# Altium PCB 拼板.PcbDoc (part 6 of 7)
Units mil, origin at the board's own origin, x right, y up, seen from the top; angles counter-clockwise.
Board outline 3630.03 x 5330.03 mil, 2 copper layers (Top Layer, Bottom Layer); 416 components, 35 nets, 1936 pads, 800 vias.
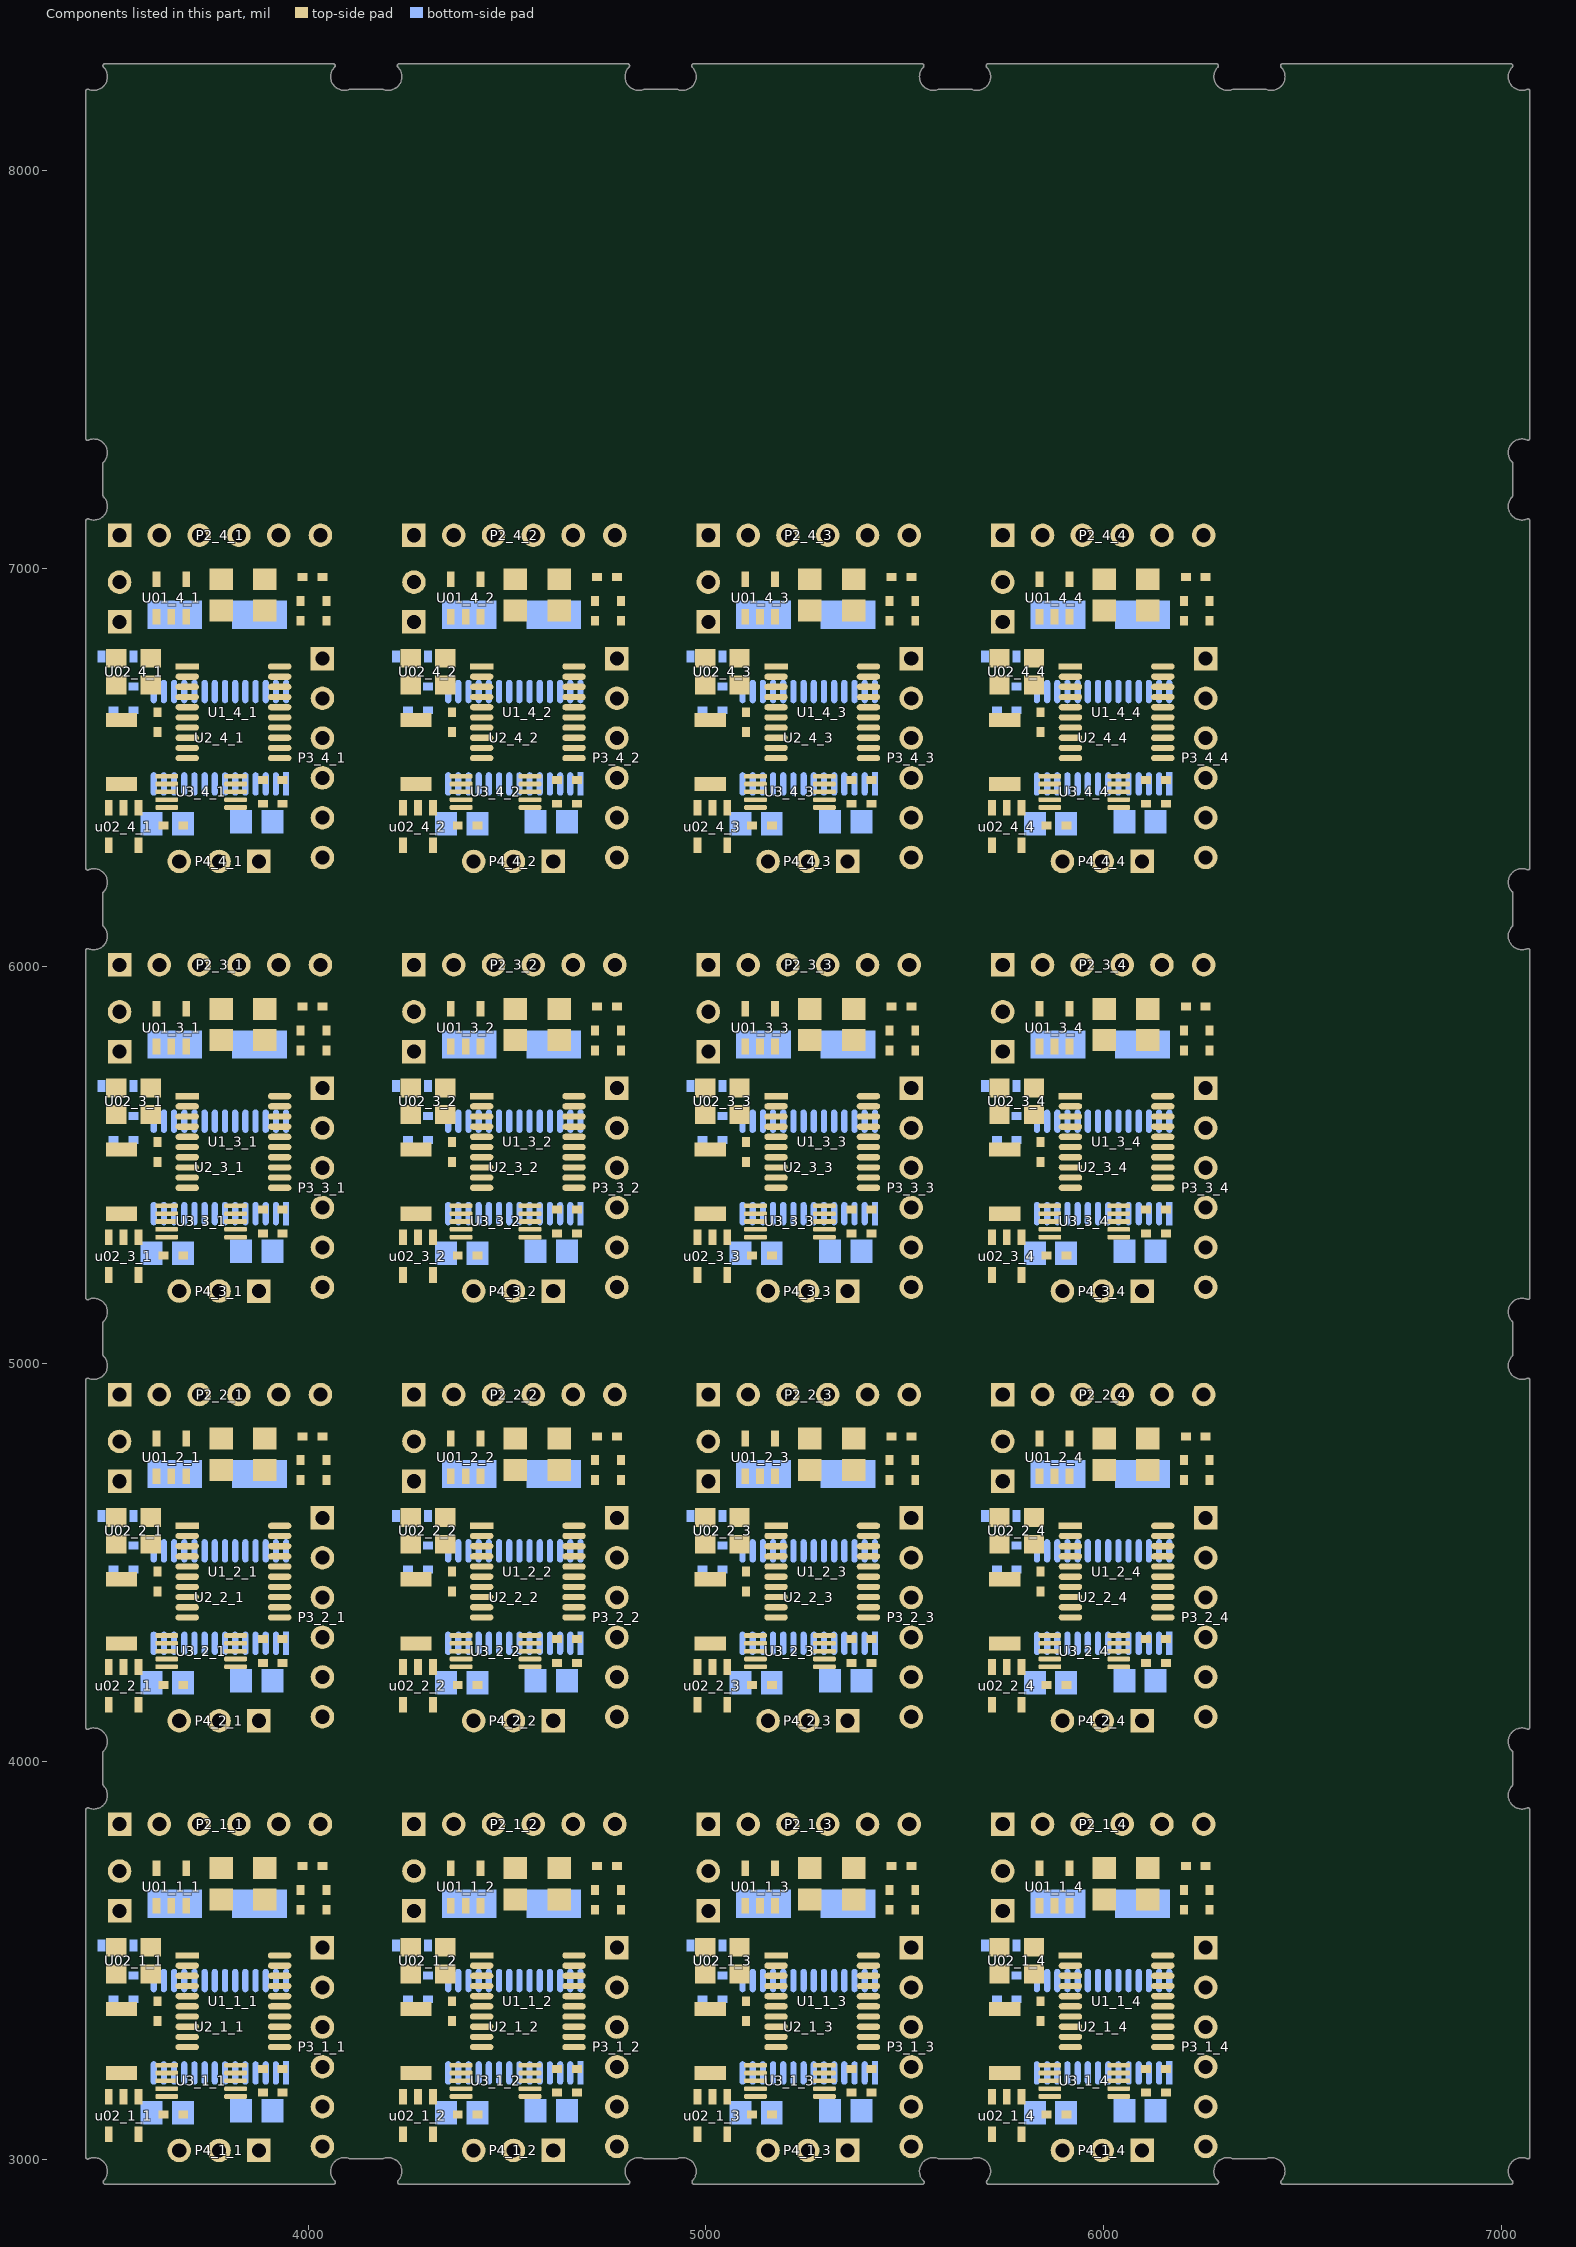
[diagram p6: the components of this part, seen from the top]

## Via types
v1: diameter 24, hole 24, Top Layer to Bottom Layer, 480 vias
v2: diameter 20, hole 10, Top Layer to Bottom Layer, 240 vias
v3: diameter 36, hole 20, Top Layer to Bottom Layer, 48 vias
v4: diameter 32, hole 16, Top Layer to Bottom Layer, 32 vias

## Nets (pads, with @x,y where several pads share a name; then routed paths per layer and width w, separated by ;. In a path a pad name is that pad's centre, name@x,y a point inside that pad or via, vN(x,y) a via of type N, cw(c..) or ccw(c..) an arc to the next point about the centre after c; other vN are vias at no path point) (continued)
copper on no net: (continued)
  Bottom Layer w20: 3506.07,3463.02 3517.35,3463.02 3542.35,3488.02 3557.28,3488.02 3592.28,3523.02 3936.07,3523.02 ; 3506.07,4543.02 3517.35,4543.02 3542.35,4568.02 3557.28,4568.02 3592.28,4603.02 3936.07,4603.02 ; 3506.07,5623.02 3517.35,5623.02 3542.35,5648.02 3557.28,5648.02 3592.28,5683.02 3936.07,5683.02 ; 3506.07,6703.02 3517.35,6703.02 3542.35,6728.02 3557.28,6728.02 3592.28,6763.02 3936.07,6763.02 ; v3(3537.32,3264.27) 3582.8,3264.27 3611.93,3235.14 3611.93,3217.74 3611.93,3123.26 3606.7,3118.02 3606.7,3029.42 3657.62,2978.49 3814.35,2978.49 ; v3(3537.32,4344.27) 3582.8,4344.27 3611.93,4315.14 3611.93,4297.74 3611.93,4203.26 3606.7,4198.02 3606.7,4109.42 3657.62,4058.49 3814.35,4058.49 ; v3(3537.32,5424.27) 3582.8,5424.27 3611.93,5395.14 3611.93,5377.74 3611.93,5283.26 3606.7,5278.02 3606.7,5189.42 3657.62,5138.49 3814.35,5138.49 ; v3(3537.32,6504.27) 3582.8,6504.27 3611.93,6475.14 3611.93,6457.74 3611.93,6363.26 3606.7,6358.02 3606.7,6269.42 3657.62,6218.49 3814.35,6218.49 ; 3664.77,3643.02 3631.3,3643.02 3605.87,3617.59 3605.87,3587.83 3561.07,3543.02 3561.07,3538.02 3556.07,3533.02 3551.07,3533.02 3522.78,3504.74 3502.78,3504.74 3466.07,3468.02 3466.07,3378.02 3491.07,3353.02 3601.07,3353.02 3693.11,3260.98 ; 3664.77,4723.02 3631.3,4723.02 3605.87,4697.59 3605.87,4667.83 3561.07,4623.02 3561.07,4618.02 3556.07,4613.02 3551.07,4613.02 3522.78,4584.74 3502.78,4584.74 3466.07,4548.02 3466.07,4458.02 3491.07,4433.02 3601.07,4433.02 3693.11,4340.98 ; 3664.77,5803.02 3631.3,5803.02 3605.87,5777.59 3605.87,5747.83 3561.07,5703.02 3561.07,5698.02 3556.07,5693.02 3551.07,5693.02 3522.78,5664.74 3502.78,5664.74 3466.07,5628.02 3466.07,5538.02 3491.07,5513.02 3601.07,5513.02 3693.11,5420.98 ; 3664.77,6883.02 3631.3,6883.02 3605.87,6857.59 3605.87,6827.83 3561.07,6783.02 3561.07,6778.02 3556.07,6773.02 3551.07,6773.02 3522.78,6744.74 3502.78,6744.74 3466.07,6708.02 3466.07,6618.02 3491.07,6593.02 3601.07,6593.02 3693.11,6500.98 ; 3688.7,3217.74 3688.7,3245.38 3688.7,3256.58 3694.39,3262.27 3772.09,3262.27 3772.84,3263.02 3854.87,3263.02 v3(3857.87,3266.02) ; 3688.7,4297.74 3688.7,4325.38 3688.7,4336.58 3694.39,4342.27 3772.09,4342.27 3772.84,4343.02 3854.87,4343.02 v3(3857.87,4346.02) ; 3688.7,5377.74 3688.7,5405.38 3688.7,5416.58 3694.39,5422.27 3772.09,5422.27 3772.84,5423.02 3854.87,5423.02 v3(3857.87,5426.02) ; 3688.7,6457.74 3688.7,6485.38 3688.7,6496.58 3694.39,6502.27 3772.09,6502.27 3772.84,6503.02 3854.87,6503.02 v3(3857.87,6506.02) ; 3739.89,3450.02 3739.89,3409.2 3801.07,3348.02 3897.28,3348.02 3944.61,3395.35 3944.61,3467.43 3972.49,3467.43 4016.54,3511.47 4016.54,3513.49 4021.07,3518.02 ; 3739.89,4530.02 3739.89,4489.2 3801.07,4428.02 3897.28,4428.02 3944.61,4475.35 3944.61,4547.43 3972.49,4547.43 4016.54,4591.47 4016.54,4593.49 4021.07,4598.02 ; 3739.89,5610.02 3739.89,5569.2 3801.07,5508.02 3897.28,5508.02 3944.61,5555.35 3944.61,5627.43 3972.49,5627.43 4016.54,5671.47 4016.54,5673.49 4021.07,5678.02 ; 3739.89,6690.02 3739.89,6649.2 3801.07,6588.02 3897.28,6588.02 3944.61,6635.35 3944.61,6707.43 3972.49,6707.43 4016.54,6751.47 4016.54,6753.49 4021.07,6758.02 ; 3791.07,3217.74 3791.07,3160.69 3789.14,3158.76 3789.14,3087.28 3797.92,3078.49 3821.07,3078.49 ; 3791.07,4297.74 3791.07,4240.69 3789.14,4238.76 3789.14,4167.28 3797.92,4158.49 3821.07,4158.49 ; 3791.07,5377.74 3791.07,5320.69 3789.14,5318.76 3789.14,5247.28 3797.92,5238.49 3821.07,5238.49 ; 3791.07,6457.74 3791.07,6400.69 3789.14,6398.76 3789.14,6327.28 3797.92,6318.49 3821.07,6318.49 ; v3@3866.88,3262.27 3867.84,3261.31 3867.84,3217.74 ; v3@3866.88,4342.27 3867.84,4341.31 3867.84,4297.74 ; v3@3866.88,5422.27 3867.84,5421.31 3867.84,5377.74 ; v3@3866.88,6502.27 3867.84,6501.31 3867.84,6457.74 ; 3877.37,3643.02 3877.37,3581.72 3936.07,3523.02 ; 3877.37,4723.02 3877.37,4661.72 3936.07,4603.02 ; 3877.37,5803.02 3877.37,5741.72 3936.07,5683.02 ; 3877.37,6883.02 3877.37,6821.72 3936.07,6763.02 ; 3910.44,3123.02 3910.44,3121.05 3867.88,3078.49 3821.07,3078.49 ; 3910.44,4203.02 3910.44,4201.05 3867.88,4158.49 3821.07,4158.49 ; 3910.44,5283.02 3910.44,5281.05 3867.88,5238.49 3821.07,5238.49 ; 3910.44,6363.02 3910.44,6361.05 3867.88,6318.49 3821.07,6318.49 ; v3(4036.07,3713.02) 4036.07,3533.02 ; v3(4036.07,4793.02) 4036.07,4613.02 ; v3(4036.07,5873.02) 4036.07,5693.02 ; v3(4036.07,6953.02) 4036.07,6773.02 ; 4246.07,3463.02 4257.35,3463.02 4282.35,3488.02 4297.28,3488.02 4332.28,3523.02 4676.07,3523.02 ; 4246.07,4543.02 4257.35,4543.02 4282.35,4568.02 4297.28,4568.02 4332.28,4603.02 4676.07,4603.02 ; 4246.07,5623.02 4257.35,5623.02 4282.35,5648.02 4297.28,5648.02 4332.28,5683.02 4676.07,5683.02 ; 4246.07,6703.02 4257.35,6703.02 4282.35,6728.02 4297.28,6728.02 4332.28,6763.02 4676.07,6763.02 ; v3(4277.32,3264.27) 4322.8,3264.27 4351.93,3235.14 4351.93,3217.74 4351.93,3123.26 4346.7,3118.02 4346.7,3029.42 4397.62,2978.49 4554.35,2978.49 ; v3(4277.32,4344.27) 4322.8,4344.27 4351.93,4315.14 4351.93,4297.74 4351.93,4203.26 4346.7,4198.02 4346.7,4109.42 4397.62,4058.49 4554.35,4058.49 ; v3(4277.32,5424.27) 4322.8,5424.27 4351.93,5395.14 4351.93,5377.74 4351.93,5283.26 4346.7,5278.02 4346.7,5189.42 4397.62,5138.49 4554.35,5138.49 ; v3(4277.32,6504.27) 4322.8,6504.27 4351.93,6475.14 4351.93,6457.74 4351.93,6363.26 4346.7,6358.02 4346.7,6269.42 4397.62,6218.49 4554.35,6218.49 ; 4404.77,3643.02 4371.3,3643.02 4345.87,3617.59 4345.87,3587.83 4301.07,3543.02 4301.07,3538.02 4296.07,3533.02 4291.07,3533.02 4262.78,3504.74 4242.78,3504.74 4206.07,3468.02 4206.07,3378.02 4231.07,3353.02 4341.07,3353.02 4433.11,3260.98 ; 4404.77,4723.02 4371.3,4723.02 4345.87,4697.59 4345.87,4667.83 4301.07,4623.02 4301.07,4618.02 4296.07,4613.02 4291.07,4613.02 4262.78,4584.74 4242.78,4584.74 4206.07,4548.02 4206.07,4458.02 4231.07,4433.02 4341.07,4433.02 4433.11,4340.98 ; 4404.77,5803.02 4371.3,5803.02 4345.87,5777.59 4345.87,5747.83 4301.07,5703.02 4301.07,5698.02 4296.07,5693.02 4291.07,5693.02 4262.78,5664.74 4242.78,5664.74 4206.07,5628.02 4206.07,5538.02 4231.07,5513.02 4341.07,5513.02 4433.11,5420.98 ; 4404.77,6883.02 4371.3,6883.02 4345.87,6857.59 4345.87,6827.83 4301.07,6783.02 4301.07,6778.02 4296.07,6773.02 4291.07,6773.02 4262.78,6744.74 4242.78,6744.74 4206.07,6708.02 4206.07,6618.02 4231.07,6593.02 4341.07,6593.02 4433.11,6500.98 ; 4428.7,3217.74 4428.7,3245.38 4428.7,3256.58 4434.39,3262.27 4512.09,3262.27 4512.84,3263.02 4594.87,3263.02 v3(4597.87,3266.02) ; 4428.7,4297.74 4428.7,4325.38 4428.7,4336.58 4434.39,4342.27 4512.09,4342.27 4512.84,4343.02 4594.87,4343.02 v3(4597.87,4346.02) ; 4428.7,5377.74 4428.7,5405.38 4428.7,5416.58 4434.39,5422.27 4512.09,5422.27 4512.84,5423.02 4594.87,5423.02 v3(4597.87,5426.02) ; 4428.7,6457.74 4428.7,6485.38 4428.7,6496.58 4434.39,6502.27 4512.09,6502.27 4512.84,6503.02 4594.87,6503.02 v3(4597.87,6506.02) ; 4479.89,3450.02 4479.89,3409.2 4541.07,3348.02 4637.28,3348.02 4684.61,3395.35 4684.61,3467.43 4712.49,3467.43 4756.54,3511.47 4756.54,3513.49 4761.07,3518.02 ; 4479.89,4530.02 4479.89,4489.2 4541.07,4428.02 4637.28,4428.02 4684.61,4475.35 4684.61,4547.43 4712.49,4547.43 4756.54,4591.47 4756.54,4593.49 4761.07,4598.02 ; 4479.89,5610.02 4479.89,5569.2 4541.07,5508.02 4637.28,5508.02 4684.61,5555.35 4684.61,5627.43 4712.49,5627.43 4756.54,5671.47 4756.54,5673.49 4761.07,5678.02 ; 4479.89,6690.02 4479.89,6649.2 4541.07,6588.02 4637.28,6588.02 4684.61,6635.35 4684.61,6707.43 4712.49,6707.43 4756.54,6751.47 4756.54,6753.49 4761.07,6758.02 ; 4531.07,3217.74 4531.07,3160.69 4529.14,3158.76 4529.14,3087.28 4537.92,3078.49 4561.07,3078.49 ; 4531.07,4297.74 4531.07,4240.69 4529.14,4238.76 4529.14,4167.28 4537.92,4158.49 4561.07,4158.49 ; 4531.07,5377.74 4531.07,5320.69 4529.14,5318.76 4529.14,5247.28 4537.92,5238.49 4561.07,5238.49 ; 4531.07,6457.74 4531.07,6400.69 4529.14,6398.76 4529.14,6327.28 4537.92,6318.49 4561.07,6318.49 ; v3@4606.88,3262.27 4607.84,3261.31 4607.84,3217.74 ; v3@4606.88,4342.27 4607.84,4341.31 4607.84,4297.74 ; v3@4606.88,5422.27 4607.84,5421.31 4607.84,5377.74 ; v3@4606.88,6502.27 4607.84,6501.31 4607.84,6457.74 ; 4617.37,3643.02 4617.37,3581.72 4676.07,3523.02 ; 4617.37,4723.02 4617.37,4661.72 4676.07,4603.02 ; 4617.37,5803.02 4617.37,5741.72 4676.07,5683.02 ; 4617.37,6883.02 4617.37,6821.72 4676.07,6763.02 ; 4650.44,3123.02 4650.44,3121.05 4607.88,3078.49 4561.07,3078.49 ; 4650.44,4203.02 4650.44,4201.05 4607.88,4158.49 4561.07,4158.49 ; 4650.44,5283.02 4650.44,5281.05 4607.88,5238.49 4561.07,5238.49 ; 4650.44,6363.02 4650.44,6361.05 4607.88,6318.49 4561.07,6318.49 ; v3(4776.07,3713.02) 4776.07,3533.02 ; v3(4776.07,4793.02) 4776.07,4613.02 ; v3(4776.07,5873.02) 4776.07,5693.02 ; v3(4776.07,6953.02) 4776.07,6773.02 ; 4986.07,3463.02 4997.35,3463.02 5022.35,3488.02 5037.28,3488.02 5072.28,3523.02 5416.07,3523.02 ; 4986.07,4543.02 4997.35,4543.02 5022.35,4568.02 5037.28,4568.02 5072.28,4603.02 5416.07,4603.02 ; 4986.07,5623.02 4997.35,5623.02 5022.35,5648.02 5037.28,5648.02 5072.28,5683.02 5416.07,5683.02 ; 4986.07,6703.02 4997.35,6703.02 5022.35,6728.02 5037.28,6728.02 5072.28,6763.02 5416.07,6763.02 ; v3(5017.32,3264.27) 5062.8,3264.27 5091.93,3235.14 5091.93,3217.74 5091.93,3123.26 5086.7,3118.02 5086.7,3029.42 5137.62,2978.49 5294.35,2978.49 ; v3(5017.32,4344.27) 5062.8,4344.27 5091.93,4315.14 5091.93,4297.74 5091.93,4203.26 5086.7,4198.02 5086.7,4109.42 5137.62,4058.49 5294.35,4058.49 ; v3(5017.32,5424.27) 5062.8,5424.27 5091.93,5395.14 5091.93,5377.74 5091.93,5283.26 5086.7,5278.02 5086.7,5189.42 5137.62,5138.49 5294.35,5138.49 ; v3(5017.32,6504.27) 5062.8,6504.27 5091.93,6475.14 5091.93,6457.74 5091.93,6363.26 5086.7,6358.02 5086.7,6269.42 5137.62,6218.49 5294.35,6218.49 ; 5144.77,3643.02 5111.3,3643.02 5085.87,3617.59 5085.87,3587.83 5041.07,3543.02 5041.07,3538.02 5036.07,3533.02 5031.07,3533.02 5002.78,3504.74 4982.78,3504.74 4946.07,3468.02 4946.07,3378.02 4971.07,3353.02 5081.07,3353.02 5173.11,3260.98 ; 5144.77,4723.02 5111.3,4723.02 5085.87,4697.59 5085.87,4667.83 5041.07,4623.02 5041.07,4618.02 5036.07,4613.02 5031.07,4613.02 5002.78,4584.74 4982.78,4584.74 4946.07,4548.02 4946.07,4458.02 4971.07,4433.02 5081.07,4433.02 5173.11,4340.98 ; 5144.77,5803.02 5111.3,5803.02 5085.87,5777.59 5085.87,5747.83 5041.07,5703.02 5041.07,5698.02 5036.07,5693.02 5031.07,5693.02 5002.78,5664.74 4982.78,5664.74 4946.07,5628.02 4946.07,5538.02 4971.07,5513.02 5081.07,5513.02 5173.11,5420.98 ; 5144.77,6883.02 5111.3,6883.02 5085.87,6857.59 5085.87,6827.83 5041.07,6783.02 5041.07,6778.02 5036.07,6773.02 5031.07,6773.02 5002.78,6744.74 4982.78,6744.74 4946.07,6708.02 4946.07,6618.02 4971.07,6593.02 5081.07,6593.02 5173.11,6500.98 ; 5168.7,3217.74 5168.7,3245.38 5168.7,3256.58 5174.39,3262.27 5252.09,3262.27 5252.84,3263.02 5334.87,3263.02 v3(5337.87,3266.02) ; 5168.7,4297.74 5168.7,4325.38 5168.7,4336.58 5174.39,4342.27 5252.09,4342.27 5252.84,4343.02 5334.87,4343.02 v3(5337.87,4346.02) ; 5168.7,5377.74 5168.7,5405.38 5168.7,5416.58 5174.39,5422.27 5252.09,5422.27 5252.84,5423.02 5334.87,5423.02 v3(5337.87,5426.02) ; 5168.7,6457.74 5168.7,6485.38 5168.7,6496.58 5174.39,6502.27 5252.09,6502.27 5252.84,6503.02 5334.87,6503.02 v3(5337.87,6506.02) ; 5219.89,3450.02 5219.89,3409.2 5281.07,3348.02 5377.28,3348.02 5424.61,3395.35 5424.61,3467.43 5452.49,3467.43 5496.54,3511.47 5496.54,3513.49 5501.07,3518.02 ; 5219.89,4530.02 5219.89,4489.2 5281.07,4428.02 5377.28,4428.02 5424.61,4475.35 5424.61,4547.43 5452.49,4547.43 5496.54,4591.47 5496.54,4593.49 5501.07,4598.02 ; 5219.89,5610.02 5219.89,5569.2 5281.07,5508.02 5377.28,5508.02 5424.61,5555.35 5424.61,5627.43 5452.49,5627.43 5496.54,5671.47 5496.54,5673.49 5501.07,5678.02 ; 5219.89,6690.02 5219.89,6649.2 5281.07,6588.02 5377.28,6588.02 5424.61,6635.35 5424.61,6707.43 5452.49,6707.43 5496.54,6751.47 5496.54,6753.49 5501.07,6758.02 ; 5271.07,3217.74 5271.07,3160.69 5269.14,3158.76 5269.14,3087.28 5277.92,3078.49 5301.07,3078.49 ; 5271.07,4297.74 5271.07,4240.69 5269.14,4238.76 5269.14,4167.28 5277.92,4158.49 5301.07,4158.49 ; 5271.07,5377.74 5271.07,5320.69 5269.14,5318.76 5269.14,5247.28 5277.92,5238.49 5301.07,5238.49 ; 5271.07,6457.74 5271.07,6400.69 5269.14,6398.76 5269.14,6327.28 5277.92,6318.49 5301.07,6318.49 ; v3@5346.88,3262.27 5347.84,3261.31 5347.84,3217.74 ; v3@5346.88,4342.27 5347.84,4341.31 5347.84,4297.74 ; v3@5346.88,5422.27 5347.84,5421.31 5347.84,5377.74 ; v3@5346.88,6502.27 5347.84,6501.31 5347.84,6457.74 ; 5357.37,3643.02 5357.37,3581.72 5416.07,3523.02 ; 5357.37,4723.02 5357.37,4661.72 5416.07,4603.02 ; 5357.37,5803.02 5357.37,5741.72 5416.07,5683.02 ; 5357.37,6883.02 5357.37,6821.72 5416.07,6763.02 ; 5390.44,3123.02 5390.44,3121.05 5347.88,3078.49 5301.07,3078.49 ; 5390.44,4203.02 5390.44,4201.05 5347.88,4158.49 5301.07,4158.49 ; 5390.44,5283.02 5390.44,5281.05 5347.88,5238.49 5301.07,5238.49 ; 5390.44,6363.02 5390.44,6361.05 5347.88,6318.49 5301.07,6318.49 ; v3(5516.07,3713.02) 5516.07,3533.02 ; v3(5516.07,4793.02) 5516.07,4613.02 ; v3(5516.07,5873.02) 5516.07,5693.02 ; v3(5516.07,6953.02) 5516.07,6773.02 ; 5726.07,3463.02 5737.35,3463.02 5762.35,3488.02 5777.28,3488.02 5812.28,3523.02 6156.07,3523.02 ; 5726.07,4543.02 5737.35,4543.02 5762.35,4568.02 5777.28,4568.02 5812.28,4603.02 6156.07,4603.02 ; 5726.07,5623.02 5737.35,5623.02 5762.35,5648.02 5777.28,5648.02 5812.28,5683.02 6156.07,5683.02 ; 5726.07,6703.02 5737.35,6703.02 5762.35,6728.02 5777.28,6728.02 5812.28,6763.02 6156.07,6763.02 ; v3(5757.32,3264.27) 5802.8,3264.27 5831.93,3235.14 5831.93,3217.74 5831.93,3123.26 5826.7,3118.02 5826.7,3029.42 5877.62,2978.49 6034.35,2978.49 ; v3(5757.32,4344.27) 5802.8,4344.27 5831.93,4315.14 5831.93,4297.74 5831.93,4203.26 5826.7,4198.02 5826.7,4109.42 5877.62,4058.49 6034.35,4058.49 ; v3(5757.32,5424.27) 5802.8,5424.27 5831.93,5395.14 5831.93,5377.74 5831.93,5283.26 5826.7,5278.02 5826.7,5189.42 5877.62,5138.49 6034.35,5138.49 ; v3(5757.32,6504.27) 5802.8,6504.27 5831.93,6475.14 5831.93,6457.74 5831.93,6363.26 5826.7,6358.02 5826.7,6269.42 5877.62,6218.49 6034.35,6218.49 ; 5884.77,3643.02 5851.3,3643.02 5825.87,3617.59 5825.87,3587.83 5781.07,3543.02 5781.07,3538.02 5776.07,3533.02 5771.07,3533.02 5742.78,3504.74 5722.78,3504.74 5686.07,3468.02 5686.07,3378.02 5711.07,3353.02 5821.07,3353.02 5913.11,3260.98 ; 5884.77,4723.02 5851.3,4723.02 5825.87,4697.59 5825.87,4667.83 5781.07,4623.02 5781.07,4618.02 5776.07,4613.02 5771.07,4613.02 5742.78,4584.74 5722.78,4584.74 5686.07,4548.02 5686.07,4458.02 5711.07,4433.02 5821.07,4433.02 5913.11,4340.98 ; 5884.77,5803.02 5851.3,5803.02 5825.87,5777.59 5825.87,5747.83 5781.07,5703.02 5781.07,5698.02 5776.07,5693.02 5771.07,5693.02 5742.78,5664.74 5722.78,5664.74 5686.07,5628.02 5686.07,5538.02 5711.07,5513.02 5821.07,5513.02 5913.11,5420.98 ; 5884.77,6883.02 5851.3,6883.02 5825.87,6857.59 5825.87,6827.83 5781.07,6783.02 5781.07,6778.02 5776.07,6773.02 5771.07,6773.02 5742.78,6744.74 5722.78,6744.74 5686.07,6708.02 5686.07,6618.02 5711.07,6593.02 5821.07,6593.02 5913.11,6500.98 ; 5908.7,3217.74 5908.7,3245.38 5908.7,3256.58 5914.39,3262.27 5992.09,3262.27 5992.84,3263.02 6074.87,3263.02 v3(6077.87,3266.02) ; 5908.7,4297.74 5908.7,4325.38 5908.7,4336.58 5914.39,4342.27 5992.09,4342.27 5992.84,4343.02 6074.87,4343.02 v3(6077.87,4346.02) ; 5908.7,5377.74 5908.7,5405.38 5908.7,5416.58 5914.39,5422.27 5992.09,5422.27 5992.84,5423.02 6074.87,5423.02 v3(6077.87,5426.02) ; 5908.7,6457.74 5908.7,6485.38 5908.7,6496.58 5914.39,6502.27 5992.09,6502.27 5992.84,6503.02 6074.87,6503.02 v3(6077.87,6506.02) ; 5959.89,3450.02 5959.89,3409.2 6021.07,3348.02 6117.28,3348.02 6164.61,3395.35 6164.61,3467.43 6192.49,3467.43 6236.54,3511.47 6236.54,3513.49 6241.07,3518.02 ; 5959.89,4530.02 5959.89,4489.2 6021.07,4428.02 6117.28,4428.02 6164.61,4475.35 6164.61,4547.43 6192.49,4547.43 6236.54,4591.47 6236.54,4593.49 6241.07,4598.02 ; 5959.89,5610.02 5959.89,5569.2 6021.07,5508.02 6117.28,5508.02 6164.61,5555.35 6164.61,5627.43 6192.49,5627.43 6236.54,5671.47 6236.54,5673.49 6241.07,5678.02 ; 5959.89,6690.02 5959.89,6649.2 6021.07,6588.02 6117.28,6588.02 6164.61,6635.35 6164.61,6707.43 6192.49,6707.43 6236.54,6751.47 6236.54,6753.49 6241.07,6758.02 ; 6011.07,3217.74 6011.07,3160.69 6009.14,3158.76 6009.14,3087.28 6017.92,3078.49 6041.07,3078.49 ; 6011.07,4297.74 6011.07,4240.69 6009.14,4238.76 6009.14,4167.28 6017.92,4158.49 6041.07,4158.49 ; 6011.07,5377.74 6011.07,5320.69 6009.14,5318.76 6009.14,5247.28 6017.92,5238.49 6041.07,5238.49 ; 6011.07,6457.74 6011.07,6400.69 6009.14,6398.76 6009.14,6327.28 6017.92,6318.49 6041.07,6318.49 ; v3@6086.88,3262.27 6087.84,3261.31 6087.84,3217.74 ; v3@6086.88,4342.27 6087.84,4341.31 6087.84,4297.74 ; v3@6086.88,5422.27 6087.84,5421.31 6087.84,5377.74 ; v3@6086.88,6502.27 6087.84,6501.31 6087.84,6457.74 ; 6097.37,3643.02 6097.37,3581.72 6156.07,3523.02 ; 6097.37,4723.02 6097.37,4661.72 6156.07,4603.02 ; 6097.37,5803.02 6097.37,5741.72 6156.07,5683.02 ; 6097.37,6883.02 6097.37,6821.72 6156.07,6763.02 ; 6130.44,3123.02 6130.44,3121.05 6087.88,3078.49 6041.07,3078.49 ; 6130.44,4203.02 6130.44,4201.05 6087.88,4158.49 6041.07,4158.49 ; 6130.44,5283.02 6130.44,5281.05 6087.88,5238.49 6041.07,5238.49 ; 6130.44,6363.02 6130.44,6361.05 6087.88,6318.49 6041.07,6318.49 ; v3(6256.07,3713.02) 6256.07,3533.02 ; v3(6256.07,4793.02) 6256.07,4613.02 ; v3(6256.07,5873.02) 6256.07,5693.02 ; v3(6256.07,6953.02) 6256.07,6773.02 ; 3814.35,2978.49 3821.07,2985.21 3821.07,3078.49 ; 3814.35,2978.49 3918.57,2978.49 4028.57,3088.49 4054.51,3088.49 4086.07,3120.05 4086.07,3483.02 4036.07,3533.02 ; 3814.35,4058.49 3821.07,4065.21 3821.07,4158.49 ; 3814.35,4058.49 3918.57,4058.49 4028.57,4168.49 4054.51,4168.49 4086.07,4200.05 4086.07,4563.02 4036.07,4613.02 ; 3814.35,5138.49 3821.07,5145.21 3821.07,5238.49 ; 3814.35,5138.49 3918.57,5138.49 4028.57,5248.49 4054.51,5248.49 4086.07,5280.05 4086.07,5643.02 4036.07,5693.02 ; 3814.35,6218.49 3821.07,6225.21 3821.07,6318.49 ; 3814.35,6218.49 3918.57,6218.49 4028.57,6328.49 4054.51,6328.49 4086.07,6360.05 4086.07,6723.02 4036.07,6773.02 ; 3936.07,3523.02 4016.54,3523.02 4021.07,3518.49 4021.07,3518.02 ; 3936.07,4603.02 4016.54,4603.02 4021.07,4598.49 4021.07,4598.02 ; 3936.07,5683.02 4016.54,5683.02 4021.07,5678.49 4021.07,5678.02 ; 3936.07,6763.02 4016.54,6763.02 4021.07,6758.49 4021.07,6758.02 ; 4021.07,3518.02 4036.07,3533.02 ; 4021.07,4598.02 4036.07,4613.02 ; 4021.07,5678.02 4036.07,5693.02 ; 4021.07,6758.02 4036.07,6773.02 ; 4554.35,2978.49 4561.07,2985.21 4561.07,3078.49 ; 4554.35,2978.49 4658.57,2978.49 4768.57,3088.49 4794.51,3088.49 4826.07,3120.05 4826.07,3483.02 4776.07,3533.02 ; 4554.35,4058.49 4561.07,4065.21 4561.07,4158.49 ; 4554.35,4058.49 4658.57,4058.49 4768.57,4168.49 4794.51,4168.49 4826.07,4200.05 4826.07,4563.02 4776.07,4613.02 ; 4554.35,5138.49 4561.07,5145.21 4561.07,5238.49 ; 4554.35,5138.49 4658.57,5138.49 4768.57,5248.49 4794.51,5248.49 4826.07,5280.05 4826.07,5643.02 4776.07,5693.02 ; 4554.35,6218.49 4561.07,6225.21 4561.07,6318.49 ; 4554.35,6218.49 4658.57,6218.49 4768.57,6328.49 4794.51,6328.49 4826.07,6360.05 4826.07,6723.02 4776.07,6773.02 ; 4676.07,3523.02 4756.54,3523.02 4761.07,3518.49 4761.07,3518.02 ; 4676.07,4603.02 4756.54,4603.02 4761.07,4598.49 4761.07,4598.02 ; 4676.07,5683.02 4756.54,5683.02 4761.07,5678.49 4761.07,5678.02 ; 4676.07,6763.02 4756.54,6763.02 4761.07,6758.49 4761.07,6758.02 ; 4761.07,3518.02 4776.07,3533.02 ; 4761.07,4598.02 4776.07,4613.02 ; 4761.07,5678.02 4776.07,5693.02 ; 4761.07,6758.02 4776.07,6773.02 ; 5294.35,2978.49 5301.07,2985.21 5301.07,3078.49 ; 5294.35,2978.49 5398.57,2978.49 5508.57,3088.49 5534.51,3088.49 5566.07,3120.05 5566.07,3483.02 5516.07,3533.02 ; 5294.35,4058.49 5301.07,4065.21 5301.07,4158.49 ; 5294.35,4058.49 5398.57,4058.49 5508.57,4168.49 5534.51,4168.49 5566.07,4200.05 5566.07,4563.02 5516.07,4613.02 ; 5294.35,5138.49 5301.07,5145.21 5301.07,5238.49 ; 5294.35,5138.49 5398.57,5138.49 5508.57,5248.49 5534.51,5248.49 5566.07,5280.05 5566.07,5643.02 5516.07,5693.02 ; 5294.35,6218.49 5301.07,6225.21 5301.07,6318.49 ; 5294.35,6218.49 5398.57,6218.49 5508.57,6328.49 5534.51,6328.49 5566.07,6360.05 5566.07,6723.02 5516.07,6773.02 ; 5416.07,3523.02 5496.54,3523.02 5501.07,3518.49 5501.07,3518.02 ; 5416.07,4603.02 5496.54,4603.02 5501.07,4598.49 5501.07,4598.02 ; 5416.07,5683.02 5496.54,5683.02 5501.07,5678.49 5501.07,5678.02 ; 5416.07,6763.02 5496.54,6763.02 5501.07,6758.49 5501.07,6758.02 ; 5501.07,3518.02 5516.07,3533.02 ; 5501.07,4598.02 5516.07,4613.02 ; 5501.07,5678.02 5516.07,5693.02 ; 5501.07,6758.02 5516.07,6773.02 ; 6034.35,2978.49 6041.07,2985.21 6041.07,3078.49 ; 6034.35,2978.49 6138.57,2978.49 6248.57,3088.49 6274.51,3088.49 6306.07,3120.05 6306.07,3483.02 6256.07,3533.02 ; 6034.35,4058.49 6041.07,4065.21 6041.07,4158.49 ; 6034.35,4058.49 6138.57,4058.49 6248.57,4168.49 6274.51,4168.49 6306.07,4200.05 6306.07,4563.02 6256.07,4613.02 ; 6034.35,5138.49 6041.07,5145.21 6041.07,5238.49 ; 6034.35,5138.49 6138.57,5138.49 6248.57,5248.49 6274.51,5248.49 6306.07,5280.05 6306.07,5643.02 6256.07,5693.02 ; 6034.35,6218.49 6041.07,6225.21 6041.07,6318.49 ; 6034.35,6218.49 6138.57,6218.49 6248.57,6328.49 6274.51,6328.49 6306.07,6360.05 6306.07,6723.02 6256.07,6773.02 ; 6156.07,3523.02 6236.54,3523.02 6241.07,3518.49 6241.07,3518.02 ; 6156.07,4603.02 6236.54,4603.02 6241.07,4598.49 6241.07,4598.02 ; 6156.07,5683.02 6236.54,5683.02 6241.07,5678.49 6241.07,5678.02 ; 6156.07,6763.02 6236.54,6763.02 6241.07,6758.49 6241.07,6758.02 ; 6241.07,3518.02 6256.07,3533.02 ; 6241.07,4598.02 6256.07,4613.02 ; 6241.07,5678.02 6256.07,5693.02 ; 6241.07,6758.02 6256.07,6773.02
  Bottom Layer w30: 3481.07,3538.02 3481.07,3580.14 3526.07,3625.14 3528.18,3623.02 ; 3481.07,4618.02 3481.07,4660.14 3526.07,4705.14 3528.18,4703.02 ; 3481.07,5698.02 3481.07,5740.14 3526.07,5785.14 3528.18,5783.02 ; 3481.07,6778.02 3481.07,6820.14 3526.07,6865.14 3528.18,6863.02 ; 4221.07,3538.02 4221.07,3580.14 4266.07,3625.14 4268.18,3623.02 ; 4221.07,4618.02 4221.07,4660.14 4266.07,4705.14 4268.18,4703.02 ; 4221.07,5698.02 4221.07,5740.14 4266.07,5785.14 4268.18,5783.02 ; 4221.07,6778.02 4221.07,6820.14 4266.07,6865.14 4268.18,6863.02 ; 4961.07,3538.02 4961.07,3580.14 5006.07,3625.14 5008.18,3623.02 ; 4961.07,4618.02 4961.07,4660.14 5006.07,4705.14 5008.18,4703.02 ; 4961.07,5698.02 4961.07,5740.14 5006.07,5785.14 5008.18,5783.02 ; 4961.07,6778.02 4961.07,6820.14 5006.07,6865.14 5008.18,6863.02 ; 5701.07,3538.02 5701.07,3580.14 5746.07,3625.14 5748.18,3623.02 ; 5701.07,4618.02 5701.07,4660.14 5746.07,4705.14 5748.18,4703.02 ; 5701.07,5698.02 5701.07,5740.14 5746.07,5785.14 5748.18,5783.02 ; 5701.07,6778.02 5701.07,6820.14 5746.07,6865.14 5748.18,6863.02
  other v1: 4116.07,3037.12 4176.07,3037.12 4856.07,3037.12 4916.07,3037.12 5596.07,3037.12 5656.07,3037.12 4116.07,3077.12 4176.07,3077.12 4856.07,3077.12 4916.07,3077.12 5596.07,3077.12 5656.07,3077.12 4116.07,3117.12 4176.07,3117.12 4856.07,3117.12 4916.07,3117.12 5596.07,3117.12 5656.07,3117.12 4116.07,3157.12 4176.07,3157.12 4856.07,3157.12 4916.07,3157.12 5596.07,3157.12 5656.07,3157.12 4116.07,3197.12 4176.07,3197.12 4856.07,3197.12 4916.07,3197.12 5596.07,3197.12 5656.07,3197.12 4116.07,3689.08 4176.07,3689.08 4856.07,3689.08 4916.07,3689.08 5596.07,3689.08 5656.07,3689.08 4116.07,3729.08 4176.07,3729.08 4856.07,3729.08 4916.07,3729.08 5596.07,3729.08 5656.07,3729.08 4116.07,3769.08 4176.07,3769.08 4856.07,3769.08 4916.07,3769.08 5596.07,3769.08 5656.07,3769.08 4116.07,3809.08 4176.07,3809.08 4856.07,3809.08 4916.07,3809.08 5596.07,3809.08 5656.07,3809.08 4116.07,3849.08 4176.07,3849.08 4856.07,3849.08 4916.07,3849.08 5596.07,3849.08 5656.07,3849.08 3519.22,3953.02 3559.22,3953.02 3599.22,3953.02 3639.22,3953.02 3679.22,3953.02 3872.91,3953.02 3912.91,3953.02 3952.91,3953.02 3992.91,3953.02 4032.91,3953.02 4259.22,3953.02 4299.22,3953.02 4339.22,3953.02 4379.22,3953.02 4419.22,3953.02 4612.91,3953.02 4652.91,3953.02 4692.91,3953.02 4732.91,3953.02 4772.91,3953.02 4999.22,3953.02 5039.22,3953.02 5079.22,3953.02 5119.22,3953.02 5159.22,3953.02 5352.91,3953.02 5392.91,3953.02 5432.91,3953.02 5472.91,3953.02 5512.91,3953.02 5739.22,3953.02 5779.22,3953.02 5819.22,3953.02 5859.22,3953.02 5899.22,3953.02 6092.91,3953.02 6132.91,3953.02 6172.91,3953.02 6212.91,3953.02 6252.91,3953.02 3519.22,4013.02 3559.22,4013.02 3599.22,4013.02 3639.22,4013.02 3679.22,4013.02 3872.91,4013.02 3912.91,4013.02 3952.91,4013.02 3992.91,4013.02 4032.91,4013.02 4259.22,4013.02 4299.22,4013.02 4339.22,4013.02 4379.22,4013.02 4419.22,4013.02 4612.91,4013.02 4652.91,4013.02 4692.91,4013.02 4732.91,4013.02 4772.91,4013.02 4999.22,4013.02 5039.22,4013.02 5079.22,4013.02 5119.22,4013.02 5159.22,4013.02 5352.91,4013.02 5392.91,4013.02 5432.91,4013.02 5472.91,4013.02 5512.91,4013.02 5739.22,4013.02 5779.22,4013.02 5819.22,4013.02 5859.22,4013.02 5899.22,4013.02 6092.91,4013.02 6132.91,4013.02 6172.91,4013.02 6212.91,4013.02 6252.91,4013.02 4116.07,4117.12 4176.07,4117.12 4856.07,4117.12 4916.07,4117.12 5596.07,4117.12 5656.07,4117.12 4116.07,4157.12 4176.07,4157.12 4856.07,4157.12 4916.07,4157.12 5596.07,4157.12 5656.07,4157.12 4116.07,4197.12 4176.07,4197.12 4856.07,4197.12 4916.07,4197.12 5596.07,4197.12 5656.07,4197.12 4116.07,4237.12 4176.07,4237.12 4856.07,4237.12 4916.07,4237.12 5596.07,4237.12 5656.07,4237.12 4116.07,4277.12 4176.07,4277.12 4856.07,4277.12 4916.07,4277.12 5596.07,4277.12 5656.07,4277.12 4116.07,4769.08 4176.07,4769.08 4856.07,4769.08 4916.07,4769.08 5596.07,4769.08 5656.07,4769.08 4116.07,4809.08 4176.07,4809.08 4856.07,4809.08 4916.07,4809.08 5596.07,4809.08 5656.07,4809.08 4116.07,4849.08 4176.07,4849.08 4856.07,4849.08 4916.07,4849.08 5596.07,4849.08 5656.07,4849.08 4116.07,4889.08 4176.07,4889.08 4856.07,4889.08 4916.07,4889.08 5596.07,4889.08 5656.07,4889.08 4116.07,4929.08 4176.07,4929.08 4856.07,4929.08 4916.07,4929.08 5596.07,4929.08 5656.07,4929.08 3519.22,5033.02 3559.22,5033.02 3599.22,5033.02 3639.22,5033.02 3679.22,5033.02 3872.91,5033.02 3912.91,5033.02 3952.91,5033.02 3992.91,5033.02 4032.91,5033.02 4259.22,5033.02 4299.22,5033.02 4339.22,5033.02 4379.22,5033.02 4419.22,5033.02 4612.91,5033.02 4652.91,5033.02 4692.91,5033.02 4732.91,5033.02 4772.91,5033.02 4999.22,5033.02 5039.22,5033.02 5079.22,5033.02 5119.22,5033.02 5159.22,5033.02 5352.91,5033.02 5392.91,5033.02 5432.91,5033.02 5472.91,5033.02 5512.91,5033.02 5739.22,5033.02 5779.22,5033.02 5819.22,5033.02 5859.22,5033.02 5899.22,5033.02 6092.91,5033.02 6132.91,5033.02 6172.91,5033.02 6212.91,5033.02 6252.91,5033.02 3519.22,5093.02 3559.22,5093.02 3599.22,5093.02 3639.22,5093.02 3679.22,5093.02 3872.91,5093.02 3912.91,5093.02 3952.91,5093.02 3992.91,5093.02 4032.91,5093.02 4259.22,5093.02 4299.22,5093.02 4339.22,5093.02 4379.22,5093.02 4419.22,5093.02 4612.91,5093.02 4652.91,5093.02 4692.91,5093.02 4732.91,5093.02 4772.91,5093.02 4999.22,5093.02 5039.22,5093.02 5079.22,5093.02 5119.22,5093.02 5159.22,5093.02 5352.91,5093.02 5392.91,5093.02 5432.91,5093.02 5472.91,5093.02 5512.91,5093.02 5739.22,5093.02 5779.22,5093.02 5819.22,5093.02 5859.22,5093.02 5899.22,5093.02 6092.91,5093.02 6132.91,5093.02 6172.91,5093.02 6212.91,5093.02 6252.91,5093.02 4116.07,5197.12 4176.07,5197.12 4856.07,5197.12 4916.07,5197.12 5596.07,5197.12 5656.07,5197.12 4116.07,5237.12 4176.07,5237.12 4856.07,5237.12 4916.07,5237.12 5596.07,5237.12 5656.07,5237.12 4116.07,5277.12 4176.07,5277.12 4856.07,5277.12 4916.07,5277.12 5596.07,5277.12 5656.07,5277.12 4116.07,5317.12 4176.07,5317.12 4856.07,5317.12 4916.07,5317.12 5596.07,5317.12 5656.07,5317.12 4116.07,5357.12 4176.07,5357.12 4856.07,5357.12 4916.07,5357.12 5596.07,5357.12 5656.07,5357.12 4116.07,5849.08 4176.07,5849.08 4856.07,5849.08 4916.07,5849.08 5596.07,5849.08 5656.07,5849.08 4116.07,5889.08 4176.07,5889.08 4856.07,5889.08 4916.07,5889.08 5596.07,5889.08 5656.07,5889.08 4116.07,5929.08 4176.07,5929.08 4856.07,5929.08 4916.07,5929.08 5596.07,5929.08 5656.07,5929.08 4116.07,5969.08 4176.07,5969.08 4856.07,5969.08 4916.07,5969.08 5596.07,5969.08 5656.07,5969.08 4116.07,6009.08 4176.07,6009.08 4856.07,6009.08 4916.07,6009.08 5596.07,6009.08 5656.07,6009.08 3519.22,6113.02 3559.22,6113.02 3599.22,6113.02 3639.22,6113.02 3679.22,6113.02 3872.91,6113.02 3912.91,6113.02 3952.91,6113.02 3992.91,6113.02 4032.91,6113.02 4259.22,6113.02 4299.22,6113.02 4339.22,6113.02 4379.22,6113.02 4419.22,6113.02 4612.91,6113.02 4652.91,6113.02 4692.91,6113.02 4732.91,6113.02 4772.91,6113.02 4999.22,6113.02 5039.22,6113.02 5079.22,6113.02 5119.22,6113.02 5159.22,6113.02 5352.91,6113.02 5392.91,6113.02 5432.91,6113.02 5472.91,6113.02 5512.91,6113.02 5739.22,6113.02 5779.22,6113.02 5819.22,6113.02 5859.22,6113.02 5899.22,6113.02 6092.91,6113.02 6132.91,6113.02 6172.91,6113.02 6212.91,6113.02 6252.91,6113.02 3519.22,6173.02 3559.22,6173.02 3599.22,6173.02 3639.22,6173.02 3679.22,6173.02 3872.91,6173.02 3912.91,6173.02 3952.91,6173.02 3992.91,6173.02 4032.91,6173.02 4259.22,6173.02 4299.22,6173.02 4339.22,6173.02 4379.22,6173.02 4419.22,6173.02 4612.91,6173.02 4652.91,6173.02 4692.91,6173.02 4732.91,6173.02 4772.91,6173.02 4999.22,6173.02 5039.22,6173.02 5079.22,6173.02 5119.22,6173.02 5159.22,6173.02 5352.91,6173.02 5392.91,6173.02 5432.91,6173.02 5472.91,6173.02 5512.91,6173.02 5739.22,6173.02 5779.22,6173.02 5819.22,6173.02 5859.22,6173.02 5899.22,6173.02 6092.91,6173.02 6132.91,6173.02 6172.91,6173.02 6212.91,6173.02 6252.91,6173.02 4116.07,6277.12 4176.07,6277.12 4856.07,6277.12 4916.07,6277.12 5596.07,6277.12 5656.07,6277.12 4116.07,6317.12 4176.07,6317.12 4856.07,6317.12 4916.07,6317.12 5596.07,6317.12 5656.07,6317.12 4116.07,6357.12 4176.07,6357.12 4856.07,6357.12 4916.07,6357.12 5596.07,6357.12 5656.07,6357.12 4116.07,6397.12 4176.07,6397.12 4856.07,6397.12 4916.07,6397.12 5596.07,6397.12 5656.07,6397.12 4116.07,6437.12 4176.07,6437.12 4856.07,6437.12 4916.07,6437.12 5596.07,6437.12 5656.07,6437.12 4116.07,6929.08 4176.07,6929.08 4856.07,6929.08 4916.07,6929.08 5596.07,6929.08 5656.07,6929.08 4116.07,6969.08 4176.07,6969.08 4856.07,6969.08 4916.07,6969.08 5596.07,6969.08 5656.07,6969.08 4116.07,7009.08 4176.07,7009.08 4856.07,7009.08 4916.07,7009.08 5596.07,7009.08 5656.07,7009.08 4116.07,7049.08 4176.07,7049.08 4856.07,7049.08 4916.07,7049.08 5596.07,7049.08 5656.07,7049.08 4116.07,7089.08 4176.07,7089.08 4856.07,7089.08 4916.07,7089.08 5596.07,7089.08 5656.07,7089.08

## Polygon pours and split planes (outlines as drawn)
no net on Top Layer "Top Layer-No Net" (solid, pour order 44): 4929.77,4083.01 cw(c4926.07,4086.39) 4921.05,4086.39 4921.05,4959.08 cw(c4926.07,4959.08) 4927.98,4963.71 ccw(c4941.11,4995.46) 4975.46,4995.46 ccw(c4941.11,4995.46) 4965.67,5019.48 ccw(c4941.11,4995.46) 4965.64,5019.51 4965.67,5019.48 cw(c4969.22,5023.02) 4964.21,5023.02 cw(c4969.22,5023.02) 4969.25,5028.04 5542.91,5028.04 cw(c5542.91,5023.02) 5547.93,5023.02 cw(c5542.91,5023.02) 5546.47,5019.49 cw(c5571.03,4995.46) 5546.49,5019.51 5546.47,5019.49 ccw(c5571.03,4995.46) 5584.15,4963.71 cw(c5586.07,4959.08) 5591.08,4959.08 cw(c5586.07,4959.08) 5591.08,4959.08 5591.08,4086.97 cw(c5586.07,4086.97) 5584.15,4082.33 ccw(c5571.03,4050.58) 5545.44,4027.65 cw(c5543.51,4023.02) 5548.53,4023.02 cw(c5543.51,4023.02) 5543.51,4018.01 5537.29,4018.01 cw(c5537.29,4023.02) 5537.29,4018.01 ccw(c5537.29,4023.02) 5537.32,4018.01 5537.29,4018.01 4970.1,4018.01 cw(c4970.1,4023.02) 4965.11,4023.49 cw(c4970.1,4023.95) 4966.41,4027.34 ccw(c4941.11,4050.58) 4975.46,4050.58 ccw(c4941.11,4050.58)
no net on Top Layer "Top Layer-No Net" (solid, pour order 42): 4929.77,3003.01 cw(c4926.07,3006.39) 4921.05,3006.39 4921.05,3879.08 cw(c4926.07,3879.08) 4927.98,3883.71 ccw(c4941.11,3915.46) 4975.46,3915.46 ccw(c4941.11,3915.46) 4965.67,3939.48 ccw(c4941.11,3915.46) 4965.64,3939.51 4965.67,3939.48 cw(c4969.22,3943.02) 4964.21,3943.02 cw(c4969.22,3943.02) 4969.25,3948.04 5542.91,3948.04 cw(c5542.91,3943.02) 5547.93,3943.02 cw(c5542.91,3943.02) 5546.47,3939.49 cw(c5571.03,3915.46) 5546.49,3939.51 5546.47,3939.49 ccw(c5571.03,3915.46) 5584.15,3883.71 cw(c5586.07,3879.08) 5591.08,3879.08 cw(c5586.07,3879.08) 5591.08,3879.08 5591.08,3006.97 cw(c5586.07,3006.97) 5584.15,3002.33 ccw(c5571.03,2970.58) 5545.44,2947.65 cw(c5543.51,2943.02) 5548.53,2943.02 cw(c5543.51,2943.02) 5543.51,2938.01 5537.29,2938.01 cw(c5537.29,2943.02) 5537.29,2938.01 ccw(c5537.29,2943.02) 5537.32,2938.01 5537.29,2938.01 4970.1,2938.01 cw(c4970.1,2943.02) 4965.11,2943.49 cw(c4970.1,2943.95) 4966.41,2947.34 ccw(c4941.11,2970.58) 4975.46,2970.58 ccw(c4941.11,2970.58)
no net on Top Layer "Top Layer-No Net" (solid, pour order 36): 4189.77,5163.01 cw(c4186.07,5166.39) 4181.05,5166.39 4181.05,6039.08 cw(c4186.07,6039.08) 4187.98,6043.71 ccw(c4201.11,6075.46) 4235.46,6075.46 ccw(c4201.11,6075.46) 4225.67,6099.48 ccw(c4201.11,6075.46) 4225.64,6099.51 4225.67,6099.48 cw(c4229.22,6103.02) 4224.21,6103.02 cw(c4229.22,6103.02) 4229.25,6108.04 4802.91,6108.04 cw(c4802.91,6103.02) 4807.93,6103.02 cw(c4802.91,6103.02) 4806.47,6099.49 cw(c4831.03,6075.46) 4806.49,6099.51 4806.47,6099.49 ccw(c4831.03,6075.46) 4844.15,6043.71 cw(c4846.07,6039.08) 4851.08,6039.08 cw(c4846.07,6039.08) 4851.08,6039.08 4851.08,5166.97 cw(c4846.07,5166.97) 4844.15,5162.33 ccw(c4831.03,5130.58) 4805.44,5107.65 cw(c4803.51,5103.02) 4808.53,5103.02 cw(c4803.51,5103.02) 4803.51,5098.01 4797.29,5098.01 cw(c4797.29,5103.02) 4797.29,5098.01 ccw(c4797.29,5103.02) 4797.32,5098.01 4797.29,5098.01 4230.1,5098.01 cw(c4230.1,5103.02) 4225.11,5103.49 cw(c4230.1,5103.95) 4226.41,5107.34 ccw(c4201.11,5130.58) 4235.46,5130.58 ccw(c4201.11,5130.58)
no net on Top Layer "Top Layer-No Net" (solid, pour order 34): 4189.77,4083.01 cw(c4186.07,4086.39) 4181.05,4086.39 4181.05,4959.08 cw(c4186.07,4959.08) 4187.98,4963.71 ccw(c4201.11,4995.46) 4235.46,4995.46 ccw(c4201.11,4995.46) 4225.67,5019.48 ccw(c4201.11,4995.46) 4225.64,5019.51 4225.67,5019.48 cw(c4229.22,5023.02) 4224.21,5023.02 cw(c4229.22,5023.02) 4229.25,5028.04 4802.91,5028.04 cw(c4802.91,5023.02) 4807.93,5023.02 cw(c4802.91,5023.02) 4806.47,5019.49 cw(c4831.03,4995.46) 4806.49,5019.51 4806.47,5019.49 ccw(c4831.03,4995.46) 4844.15,4963.71 cw(c4846.07,4959.08) 4851.08,4959.08 cw(c4846.07,4959.08) 4851.08,4959.08 4851.08,4086.97 cw(c4846.07,4086.97) 4844.15,4082.33 ccw(c4831.03,4050.58) 4805.44,4027.65 cw(c4803.51,4023.02) 4808.53,4023.02 cw(c4803.51,4023.02) 4803.51,4018.01 4797.29,4018.01 cw(c4797.29,4023.02) 4797.29,4018.01 ccw(c4797.29,4023.02) 4797.32,4018.01 4797.29,4018.01 4230.1,4018.01 cw(c4230.1,4023.02) 4225.11,4023.49 cw(c4230.1,4023.95) 4226.41,4027.34 ccw(c4201.11,4050.58) 4235.46,4050.58 ccw(c4201.11,4050.58)
no net on Top Layer "Top Layer-No Net" (solid, pour order 32): 4189.77,3003.01 cw(c4186.07,3006.39) 4181.05,3006.39 4181.05,3879.08 cw(c4186.07,3879.08) 4187.98,3883.71 ccw(c4201.11,3915.46) 4235.46,3915.46 ccw(c4201.11,3915.46) 4225.67,3939.48 ccw(c4201.11,3915.46) 4225.64,3939.51 4225.67,3939.48 cw(c4229.22,3943.02) 4224.21,3943.02 cw(c4229.22,3943.02) 4229.25,3948.04 4802.91,3948.04 cw(c4802.91,3943.02) 4807.93,3943.02 cw(c4802.91,3943.02) 4806.47,3939.49 cw(c4831.03,3915.46) 4806.49,3939.51 4806.47,3939.49 ccw(c4831.03,3915.46) 4844.15,3883.71 cw(c4846.07,3879.08) 4851.08,3879.08 cw(c4846.07,3879.08) 4851.08,3879.08 4851.08,3006.97 cw(c4846.07,3006.97) 4844.15,3002.33 ccw(c4831.03,2970.58) 4805.44,2947.65 cw(c4803.51,2943.02) 4808.53,2943.02 cw(c4803.51,2943.02) 4803.51,2938.01 4797.29,2938.01 cw(c4797.29,2943.02) 4797.29,2938.01 ccw(c4797.29,2943.02) 4797.32,2938.01 4797.29,2938.01 4230.1,2938.01 cw(c4230.1,2943.02) 4225.11,2943.49 cw(c4230.1,2943.95) 4226.41,2947.34 ccw(c4201.11,2970.58) 4235.46,2970.58 ccw(c4201.11,2970.58)
no net on Top Layer "Top Layer-No Net" (solid, pour order 26): 3449.77,5163.01 cw(c3446.07,5166.39) 3441.05,5166.39 3441.05,6039.08 cw(c3446.07,6039.08) 3447.98,6043.71 ccw(c3461.11,6075.46) 3495.46,6075.46 ccw(c3461.11,6075.46) 3485.67,6099.48 ccw(c3461.11,6075.46) 3485.64,6099.51 3485.67,6099.48 cw(c3489.22,6103.02) 3484.21,6103.02 cw(c3489.22,6103.02) 3489.25,6108.04 4062.91,6108.04 cw(c4062.91,6103.02) 4067.93,6103.02 cw(c4062.91,6103.02) 4066.47,6099.49 cw(c4091.03,6075.46) 4066.49,6099.51 4066.47,6099.49 ccw(c4091.03,6075.46) 4104.15,6043.71 cw(c4106.07,6039.08) 4111.08,6039.08 cw(c4106.07,6039.08) 4111.08,6039.08 4111.08,5166.97 cw(c4106.07,5166.97) 4104.15,5162.33 ccw(c4091.03,5130.58) 4065.44,5107.65 cw(c4063.51,5103.02) 4068.53,5103.02 cw(c4063.51,5103.02) 4063.51,5098.01 4057.29,5098.01 cw(c4057.29,5103.02) 4057.29,5098.01 ccw(c4057.29,5103.02) 4057.32,5098.01 4057.29,5098.01 3490.1,5098.01 cw(c3490.1,5103.02) 3485.11,5103.49 cw(c3490.1,5103.95) 3486.41,5107.34 ccw(c3461.11,5130.58) 3495.46,5130.58 ccw(c3461.11,5130.58)
no net on Top Layer "Top Layer-No Net" (solid, pour order 24): 3449.77,4083.01 cw(c3446.07,4086.39) 3441.05,4086.39 3441.05,4959.08 cw(c3446.07,4959.08) 3447.98,4963.71 ccw(c3461.11,4995.46) 3495.46,4995.46 ccw(c3461.11,4995.46) 3485.67,5019.48 ccw(c3461.11,4995.46) 3485.64,5019.51 3485.67,5019.48 cw(c3489.22,5023.02) 3484.21,5023.02 cw(c3489.22,5023.02) 3489.25,5028.04 4062.91,5028.04 cw(c4062.91,5023.02) 4067.93,5023.02 cw(c4062.91,5023.02) 4066.47,5019.49 cw(c4091.03,4995.46) 4066.49,5019.51 4066.47,5019.49 ccw(c4091.03,4995.46) 4104.15,4963.71 cw(c4106.07,4959.08) 4111.08,4959.08 cw(c4106.07,4959.08) 4111.08,4959.08 4111.08,4086.97 cw(c4106.07,4086.97) 4104.15,4082.33 ccw(c4091.03,4050.58) 4065.44,4027.65 cw(c4063.51,4023.02) 4068.53,4023.02 cw(c4063.51,4023.02) 4063.51,4018.01 4057.29,4018.01 cw(c4057.29,4023.02) 4057.29,4018.01 ccw(c4057.29,4023.02) 4057.32,4018.01 4057.29,4018.01 3490.1,4018.01 cw(c3490.1,4023.02) 3485.11,4023.49 cw(c3490.1,4023.95) 3486.41,4027.34 ccw(c3461.11,4050.58) 3495.46,4050.58 ccw(c3461.11,4050.58)
no net on Top Layer "Top Layer-No Net" (solid, pour order 22): 3449.77,3003.01 cw(c3446.07,3006.39) 3441.05,3006.39 3441.05,3879.08 cw(c3446.07,3879.08) 3447.98,3883.71 ccw(c3461.11,3915.46) 3495.46,3915.46 ccw(c3461.11,3915.46) 3485.67,3939.48 ccw(c3461.11,3915.46) 3485.64,3939.51 3485.67,3939.48 cw(c3489.22,3943.02) 3484.21,3943.02 cw(c3489.22,3943.02) 3489.25,3948.04 4062.91,3948.04 cw(c4062.91,3943.02) 4067.93,3943.02 cw(c4062.91,3943.02) 4066.47,3939.49 cw(c4091.03,3915.46) 4066.49,3939.51 4066.47,3939.49 ccw(c4091.03,3915.46) 4104.15,3883.71 cw(c4106.07,3879.08) 4111.08,3879.08 cw(c4106.07,3879.08) 4111.08,3879.08 4111.08,3006.97 cw(c4106.07,3006.97) 4104.15,3002.33 ccw(c4091.03,2970.58) 4065.44,2947.65 cw(c4063.51,2943.02) 4068.53,2943.02 cw(c4063.51,2943.02) 4063.51,2938.01 4057.29,2938.01 cw(c4057.29,2943.02) 4057.29,2938.01 ccw(c4057.29,2943.02) 4057.32,2938.01 4057.29,2938.01 3490.1,2938.01 cw(c3490.1,2943.02) 3485.11,2943.49 cw(c3490.1,2943.95) 3486.41,2947.34 ccw(c3461.11,2970.58) 3495.46,2970.58 ccw(c3461.11,2970.58)
no net on Top Layer "Top Layer-No Net" (solid, pour order 46): 4929.77,5163.01 cw(c4926.07,5166.39) 4921.05,5166.39 4921.05,6039.08 cw(c4926.07,6039.08) 4927.98,6043.71 ccw(c4941.11,6075.46) 4975.46,6075.46 ccw(c4941.11,6075.46) 4965.67,6099.48 ccw(c4941.11,6075.46) 4965.64,6099.51 4965.67,6099.48 cw(c4969.22,6103.02) 4964.21,6103.02 cw(c4969.22,6103.02) 4969.25,6108.04 5542.91,6108.04 cw(c5542.91,6103.02) 5547.93,6103.02 cw(c5542.91,6103.02) 5546.47,6099.49 cw(c5571.03,6075.46) 5546.49,6099.51 5546.47,6099.49 ccw(c5571.03,6075.46) 5584.15,6043.71 cw(c5586.07,6039.08) 5591.08,6039.08 cw(c5586.07,6039.08) 5591.08,6039.08 5591.08,5166.97 cw(c5586.07,5166.97) 5584.15,5162.33 ccw(c5571.03,5130.58) 5545.44,5107.65 cw(c5543.51,5103.02) 5548.53,5103.02 cw(c5543.51,5103.02) 5543.51,5098.01 5537.29,5098.01 cw(c5537.29,5103.02) 5537.29,5098.01 ccw(c5537.29,5103.02) 5537.32,5098.01 5537.29,5098.01 4970.1,5098.01 cw(c4970.1,5103.02) 4965.11,5103.49 cw(c4970.1,5103.95) 4966.41,5107.34 ccw(c4941.11,5130.58) 4975.46,5130.58 ccw(c4941.11,5130.58)
no net on Top Layer "Top Layer-No Net" (solid, pour order 58): 5669.77,6243.01 cw(c5666.07,6246.39) 5661.05,6246.39 5661.05,7119.08 cw(c5666.07,7119.08) 5667.98,7123.71 ccw(c5681.11,7155.46) 5715.46,7155.46 ccw(c5681.11,7155.46) 5705.67,7179.48 ccw(c5681.11,7155.46) 5705.64,7179.51 5705.67,7179.48 cw(c5709.22,7183.02) 5704.21,7183.02 cw(c5709.22,7183.02) 5709.25,7188.04 6282.91,7188.04 cw(c6282.91,7183.02) 6287.93,7183.02 cw(c6282.91,7183.02) 6286.47,7179.49 cw(c6311.03,7155.46) 6286.49,7179.51 6286.47,7179.49 ccw(c6311.03,7155.46) 6324.15,7123.71 cw(c6326.07,7119.08) 6331.08,7119.08 cw(c6326.07,7119.08) 6331.08,7119.08 6331.08,6246.97 cw(c6326.07,6246.97) 6324.15,6242.33 ccw(c6311.03,6210.58) 6285.44,6187.65 cw(c6283.51,6183.02) 6288.53,6183.02 cw(c6283.51,6183.02) 6283.51,6178.01 6277.29,6178.01 cw(c6277.29,6183.02) 6277.29,6178.01 ccw(c6277.29,6183.02) 6277.32,6178.01 6277.29,6178.01 5710.1,6178.01 cw(c5710.1,6183.02) 5705.11,6183.49 cw(c5710.1,6183.95) 5706.41,6187.34 ccw(c5681.11,6210.58) 5715.46,6210.58 ccw(c5681.11,6210.58)
no net on Top Layer "Top Layer-No Net" (solid, pour order 48): 4929.77,6243.01 cw(c4926.07,6246.39) 4921.05,6246.39 4921.05,7119.08 cw(c4926.07,7119.08) 4927.98,7123.71 ccw(c4941.11,7155.46) 4975.46,7155.46 ccw(c4941.11,7155.46) 4965.67,7179.48 ccw(c4941.11,7155.46) 4965.64,7179.51 4965.67,7179.48 cw(c4969.22,7183.02) 4964.21,7183.02 cw(c4969.22,7183.02) 4969.25,7188.04 5542.91,7188.04 cw(c5542.91,7183.02) 5547.93,7183.02 cw(c5542.91,7183.02) 5546.47,7179.49 cw(c5571.03,7155.46) 5546.49,7179.51 5546.47,7179.49 ccw(c5571.03,7155.46) 5584.15,7123.71 cw(c5586.07,7119.08) 5591.08,7119.08 cw(c5586.07,7119.08) 5591.08,7119.08 5591.08,6246.97 cw(c5586.07,6246.97) 5584.15,6242.33 ccw(c5571.03,6210.58) 5545.44,6187.65 cw(c5543.51,6183.02) 5548.53,6183.02 cw(c5543.51,6183.02) 5543.51,6178.01 5537.29,6178.01 cw(c5537.29,6183.02) 5537.29,6178.01 ccw(c5537.29,6183.02) 5537.32,6178.01 5537.29,6178.01 4970.1,6178.01 cw(c4970.1,6183.02) 4965.11,6183.49 cw(c4970.1,6183.95) 4966.41,6187.34 ccw(c4941.11,6210.58) 4975.46,6210.58 ccw(c4941.11,6210.58)
no net on Top Layer "Top Layer-No Net" (solid, pour order 38): 4189.77,6243.01 cw(c4186.07,6246.39) 4181.05,6246.39 4181.05,7119.08 cw(c4186.07,7119.08) 4187.98,7123.71 ccw(c4201.11,7155.46) 4235.46,7155.46 ccw(c4201.11,7155.46) 4225.67,7179.48 ccw(c4201.11,7155.46) 4225.64,7179.51 4225.67,7179.48 cw(c4229.22,7183.02) 4224.21,7183.02 cw(c4229.22,7183.02) 4229.25,7188.04 4802.91,7188.04 cw(c4802.91,7183.02) 4807.93,7183.02 cw(c4802.91,7183.02) 4806.47,7179.49 cw(c4831.03,7155.46) 4806.49,7179.51 4806.47,7179.49 ccw(c4831.03,7155.46) 4844.15,7123.71 cw(c4846.07,7119.08) 4851.08,7119.08 cw(c4846.07,7119.08) 4851.08,7119.08 4851.08,6246.97 cw(c4846.07,6246.97) 4844.15,6242.33 ccw(c4831.03,6210.58) 4805.44,6187.65 cw(c4803.51,6183.02) 4808.53,6183.02 cw(c4803.51,6183.02) 4803.51,6178.01 4797.29,6178.01 cw(c4797.29,6183.02) 4797.29,6178.01 ccw(c4797.29,6183.02) 4797.32,6178.01 4797.29,6178.01 4230.1,6178.01 cw(c4230.1,6183.02) 4225.11,6183.49 cw(c4230.1,6183.95) 4226.41,6187.34 ccw(c4201.11,6210.58) 4235.46,6210.58 ccw(c4201.11,6210.58)
no net on Top Layer "Top Layer-No Net" (solid, pour order 28): 3449.77,6243.01 cw(c3446.07,6246.39) 3441.05,6246.39 3441.05,7119.08 cw(c3446.07,7119.08) 3447.98,7123.71 ccw(c3461.11,7155.46) 3495.46,7155.46 ccw(c3461.11,7155.46) 3485.67,7179.48 ccw(c3461.11,7155.46) 3485.64,7179.51 3485.67,7179.48 cw(c3489.22,7183.02) 3484.21,7183.02 cw(c3489.22,7183.02) 3489.25,7188.04 4062.91,7188.04 cw(c4062.91,7183.02) 4067.93,7183.02 cw(c4062.91,7183.02) 4066.47,7179.49 cw(c4091.03,7155.46) 4066.49,7179.51 4066.47,7179.49 ccw(c4091.03,7155.46) 4104.15,7123.71 cw(c4106.07,7119.08) 4111.08,7119.08 cw(c4106.07,7119.08) 4111.08,7119.08 4111.08,6246.97 cw(c4106.07,6246.97) 4104.15,6242.33 ccw(c4091.03,6210.58) 4065.44,6187.65 cw(c4063.51,6183.02) 4068.53,6183.02 cw(c4063.51,6183.02) 4063.51,6178.01 4057.29,6178.01 cw(c4057.29,6183.02) 4057.29,6178.01 ccw(c4057.29,6183.02) 4057.32,6178.01 4057.29,6178.01 3490.1,6178.01 cw(c3490.1,6183.02) 3485.11,6183.49 cw(c3490.1,6183.95) 3486.41,6187.34 ccw(c3461.11,6210.58) 3495.46,6210.58 ccw(c3461.11,6210.58)
no net on Top Layer "Top Layer-No Net" (solid, pour order 56): 5669.77,5163.01 cw(c5666.07,5166.39) 5661.05,5166.39 5661.05,6039.08 cw(c5666.07,6039.08) 5667.98,6043.71 ccw(c5681.11,6075.46) 5715.46,6075.46 ccw(c5681.11,6075.46) 5705.67,6099.48 ccw(c5681.11,6075.46) 5705.64,6099.51 5705.67,6099.48 cw(c5709.22,6103.02) 5704.21,6103.02 cw(c5709.22,6103.02) 5709.25,6108.04 6282.91,6108.04 cw(c6282.91,6103.02) 6287.93,6103.02 cw(c6282.91,6103.02) 6286.47,6099.49 cw(c6311.03,6075.46) 6286.49,6099.51 6286.47,6099.49 ccw(c6311.03,6075.46) 6324.15,6043.71 cw(c6326.07,6039.08) 6331.08,6039.08 cw(c6326.07,6039.08) 6331.08,6039.08 6331.08,5166.97 cw(c6326.07,5166.97) 6324.15,5162.33 ccw(c6311.03,5130.58) 6285.44,5107.65 cw(c6283.51,5103.02) 6288.53,5103.02 cw(c6283.51,5103.02) 6283.51,5098.01 6277.29,5098.01 cw(c6277.29,5103.02) 6277.29,5098.01 ccw(c6277.29,5103.02) 6277.32,5098.01 6277.29,5098.01 5710.1,5098.01 cw(c5710.1,5103.02) 5705.11,5103.49 cw(c5710.1,5103.95) 5706.41,5107.34 ccw(c5681.11,5130.58) 5715.46,5130.58 ccw(c5681.11,5130.58)
no net on Top Layer "Top Layer-No Net" (solid, pour order 52): 5669.77,3003.01 cw(c5666.07,3006.39) 5661.05,3006.39 5661.05,3879.08 cw(c5666.07,3879.08) 5667.98,3883.71 ccw(c5681.11,3915.46) 5715.46,3915.46 ccw(c5681.11,3915.46) 5705.67,3939.48 ccw(c5681.11,3915.46) 5705.64,3939.51 5705.67,3939.48 cw(c5709.22,3943.02) 5704.21,3943.02 cw(c5709.22,3943.02) 5709.25,3948.04 6282.91,3948.04 cw(c6282.91,3943.02) 6287.93,3943.02 cw(c6282.91,3943.02) 6286.47,3939.49 cw(c6311.03,3915.46) 6286.49,3939.51 6286.47,3939.49 ccw(c6311.03,3915.46) 6324.15,3883.71 cw(c6326.07,3879.08) 6331.08,3879.08 cw(c6326.07,3879.08) 6331.08,3879.08 6331.08,3006.97 cw(c6326.07,3006.97) 6324.15,3002.33 ccw(c6311.03,2970.58) 6285.44,2947.65 cw(c6283.51,2943.02) 6288.53,2943.02 cw(c6283.51,2943.02) 6283.51,2938.01 6277.29,2938.01 cw(c6277.29,2943.02) 6277.29,2938.01 ccw(c6277.29,2943.02) 6277.32,2938.01 6277.29,2938.01 5710.1,2938.01 cw(c5710.1,2943.02) 5705.11,2943.49 cw(c5710.1,2943.95) 5706.41,2947.34 ccw(c5681.11,2970.58) 5715.46,2970.58 ccw(c5681.11,2970.58)
no net on Top Layer "Top Layer-No Net" (solid, pour order 54): 5669.77,4083.01 cw(c5666.07,4086.39) 5661.05,4086.39 5661.05,4959.08 cw(c5666.07,4959.08) 5667.98,4963.71 ccw(c5681.11,4995.46) 5715.46,4995.46 ccw(c5681.11,4995.46) 5705.67,5019.48 ccw(c5681.11,4995.46) 5705.64,5019.51 5705.67,5019.48 cw(c5709.22,5023.02) 5704.21,5023.02 cw(c5709.22,5023.02) 5709.25,5028.04 6282.91,5028.04 cw(c6282.91,5023.02) 6287.93,5023.02 cw(c6282.91,5023.02) 6286.47,5019.49 cw(c6311.03,4995.46) 6286.49,5019.51 6286.47,5019.49 ccw(c6311.03,4995.46) 6324.15,4963.71 cw(c6326.07,4959.08) 6331.08,4959.08 cw(c6326.07,4959.08) 6331.08,4959.08 6331.08,4086.97 cw(c6326.07,4086.97) 6324.15,4082.33 ccw(c6311.03,4050.58) 6285.44,4027.65 cw(c6283.51,4023.02) 6288.53,4023.02 cw(c6283.51,4023.02) 6283.51,4018.01 6277.29,4018.01 cw(c6277.29,4023.02) 6277.29,4018.01 ccw(c6277.29,4023.02) 6277.32,4018.01 6277.29,4018.01 5710.1,4018.01 cw(c5710.1,4023.02) 5705.11,4023.49 cw(c5710.1,4023.95) 5706.41,4027.34 ccw(c5681.11,4050.58) 5715.46,4050.58 ccw(c5681.11,4050.58)
no net on Bottom Layer "Top Layer-No Net1" (solid, pour order 45): 4929.77,4083.01 cw(c4926.07,4086.39) 4921.05,4086.39 4921.05,4959.08 cw(c4926.07,4959.08) 4927.98,4963.71 ccw(c4941.11,4995.46) 4975.46,4995.46 ccw(c4941.11,4995.46) 4965.67,5019.48 ccw(c4941.11,4995.46) 4965.64,5019.51 4965.67,5019.48 cw(c4969.22,5023.02) 4964.21,5023.02 cw(c4969.22,5023.02) 4969.25,5028.04 5542.91,5028.04 cw(c5542.91,5023.02) 5547.93,5023.02 cw(c5542.91,5023.02) 5546.47,5019.49 cw(c5571.03,4995.46) 5546.49,5019.51 5546.47,5019.49 ccw(c5571.03,4995.46) 5584.15,4963.71 cw(c5586.07,4959.08) 5591.08,4959.08 cw(c5586.07,4959.08) 5591.08,4959.08 5591.08,4086.97 cw(c5586.07,4086.97) 5584.15,4082.33 ccw(c5571.03,4050.58) 5545.44,4027.65 cw(c5543.51,4023.02) 5548.53,4023.02 cw(c5543.51,4023.02) 5543.51,4018.01 5537.29,4018.01 cw(c5537.29,4023.02) 5537.29,4018.01 ccw(c5537.29,4023.02) 5537.32,4018.01 5537.29,4018.01 4970.1,4018.01 cw(c4970.1,4023.02) 4965.11,4023.49 cw(c4970.1,4023.95) 4966.41,4027.34 ccw(c4941.11,4050.58) 4975.46,4050.58 ccw(c4941.11,4050.58)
